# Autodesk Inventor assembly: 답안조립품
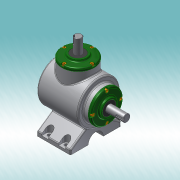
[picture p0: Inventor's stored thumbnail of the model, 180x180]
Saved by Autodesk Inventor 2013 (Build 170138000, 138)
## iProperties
Created: 2017-04
Part Number: 답안조립품
Document SubType Name: Assembly
Designer: dgall
Author: dgall
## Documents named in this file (14)
- C:\Users\dgall\Desktop\470407V1014\답안조립품.iam
- C:\Users\dgall\Desktop\470407V1014\본체.ipt
- C:\Users\dgall\Desktop\470407V1014\메인 베벨기어.ipt
- C:\Users\dgall\Desktop\470407V1014\메인 축.ipt
- 메인 축.ipt
- C:\Users\dgall\Desktop\470407V1014\베어링 6203.ipt
- C:\Users\dgall\Desktop\470407V1014\볼트 M4.ipt
- C:\Users\dgall\Desktop\470407V1014\서브 베벨기어.ipt
- C:\Users\dgall\Desktop\470407V1014\서브 축.ipt
- 서브 축.ipt
- C:\Users\dgall\Desktop\470407V1014\오일실 17 32 8.ipt
- C:\Users\dgall\Desktop\470407V1014\커버.ipt
- C:\Users\dgall\Desktop\470407V1014\키 4x4.ipt
- C:\Users\dgall\Desktop\470407V1014\키 5x5.ipt
